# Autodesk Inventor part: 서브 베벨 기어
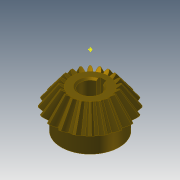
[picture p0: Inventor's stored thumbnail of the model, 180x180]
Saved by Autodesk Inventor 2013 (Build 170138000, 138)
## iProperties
Created: 2014-10
Part Number: 서브 베벨 기어
Material: Steel, Mild
Document SubType Name: Modeling
Designer: KYOUNG IL JANG
Categories: <?xml version="1.0" encoding="UTF-16"?> <MemberInstance><Categories><FamilyTemplate><FamilyTemplateParameter ValueType="xs:double" Id="1" ObjectReferenceKey="da
Mass: 134.866 g
Surface Area: 63.6518 cm^2
Volume: 17.1585 cm^3
Density: 7.86 g/cm^3
CustomPartVersion: 1
Company: 한국ATC센터
Author: KYOUNG IL JANG
Revision Number: 1
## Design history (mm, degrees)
node "맨 위 점"
node "메쉬 평면2"
sketch "톱니 본체 스케치"
  geometry: L1 (0, 0)-(18.003, -31.331); L2 (18.003, -31.331)-(21.664, -28.891); L3 (21.664, -28.891)-(0, 0); L4 (20, -30)-(0, 0); L5 (10.813, -18.818)-(13.012, -17.352); L6 (18.003, -31.331)-(10.813, -18.818); L7 (21.664, -28.891)-(13.012, -17.352); L8 (0, -39.387)-(0, 6.564) reference; L9 (0, -30)-(21.664, -30)
  constraints: 16 end point, 4 point on line, 3 perpendicular, 2 collinear, 1 horizontal alignment, 1 vertical alignment
  dimensions: "d0" = 40 diameter of L4.start L8 (= da_de); "d1" = 36.00616 diameter of L1.end L8 (= da_dfe); "d2" = 43.3282 diameter of L2.end L8 (= da_dae); "d3" = 14.4 distance between parallel lines of L2 L5 (= da_b); "d4" = 28.8906 vertical distance of L2.end L1.start (= da_ve)
revolve "톱니 본체" sketch "톱니 본체 스케치" stored, may be unused: angle "d5" = 90 deg
node "시작점"
node "톱니 평면"
sketch "시작 스케치"
  geometry: L1 (0, -23.505)-(0, 10.645) reference; L2 (-0.834, -2.928)-(0.834, -2.928); A1 r 8.898 centre (-9.698, -3.713) between (-0.834, -2.928) and (-3.903, 3.04); A2 r 8.898 centre (9.698, -3.713) between (3.903, 3.04) and (0.834, -2.928); A3 r 27.357 centre (0, -24.037) between (3.903, 3.04) and (-3.903, 3.04); 1 further point
  constraints: 6 point on circle, 3 centre point, 3 symmetric about line, 2 end point, 1 coincident, 1 perpendicular, 1 other
  dimensions: "d7" = 8.89846 radius of A1 (= fd_rr); "d8" = 9.69794 horizontal distance of point (0, -24.037) A1.centre (= fd_x); "d9" = 20.32439 vertical distance of point (0, -24.037) A1.centre (= fd_y); "d57" = 27.35701 radius of A3 (= 0.5 x fd_dva + 0.3 x da_he); "d58" = 21.10901 distance from line of A3.centre L2 (= 0.5 x fd_dva - 1.12 x da_he)
node "끝점"
  node "끝 평면"
sketch "3D 스케치 오른쪽"
  node "Helical Curve Right" dims "d65" = 229.90621 (computed from da_dm, da_delta, da_beta), "d66" = 31.5, "d67" = 40 (= da_de), "d68" = -5.88003 (= -da_delta), "d69" = 12.16458 (computed from fd_loft, da_delta)
node "끝 평면 오른쪽"
sketch "끝 스케치 오른쪽"
  geometry: L1 (0, -22.649)-(0, 12.15) reference; L2 (-0.497, -1.72)-(0.497, -1.72); A1 r 5.299 centre (-5.775, -2.187) between (-0.497, -1.72) and (-2.324, 1.834); A2 r 5.299 centre (5.775, -2.187) between (2.324, 1.834) and (0.497, -1.72); A3 r 16.291 centre (0, -14.29) between (2.324, 1.834) and (-2.324, 1.834); 1 further point
  constraints: 6 point on circle, 3 centre point, 3 symmetric about line, 2 end point, 1 coincident, 1 perpendicular, 1 other
  dimensions: "d70" = 5.77526 horizontal distance of A3.centre A1.centre (computed from fd_x, fd_ratio); "d71" = 12.10346 vertical distance of point (0, -14.29) A1.centre (computed from fd_y, fd_ratio); "d72" = 5.29916 radius of A1 (computed from fd_rr, fd_ratio); "d73" = 12.57071 distance from line of point (0, -14.29) L2 (computed from d58, fd_ratio); "d74" = 16.29149 radius of A3 (computed from d57, fd_ratio)
feature "로프트 오른쪽" sketch "끝 스케치 오른쪽" dims "d75" = 0, "d77" = 0, "d79" = 0, "d80" = 90 deg, "d85" = 20, "d92" = 90 deg, "d93" = 90 deg, "da_teethtype" = 0 [user parameter]
sketch "3D 스케치 왼쪽"
  node "Helical Curve Left" dims "d26" = 229.90621 (computed from da_dm, da_delta, da_beta), "d27" = 12.16458 (computed from fd_loft, da_delta), "d28" = 40 (= da_de), "d29" = -5.88003 (= -da_delta)
node "끝 평면 왼쪽"
sketch "끝 스케치 왼쪽" dims "d56" = 10.82768 (derived)
  geometry: L1 (0, -35.087)-(0, 18.089) reference; L2 (-0.497, -1.716)-(0.497, -1.716); A1 r 5.299 centre (-5.775, -2.183) between (-0.497, -1.716) and (-2.324, 1.838); A2 r 5.299 centre (5.775, -2.183) between (2.324, 1.838) and (0.497, -1.716); A3 r 16.291 centre (0, -14.287) between (2.324, 1.838) and (-2.324, 1.838); 2 further points; 1 other entity
  constraints: 6 point on circle, 3 centre point, 3 symmetric about line, 2 end point, 1 coincident, 2 other
  dimensions: "d30" = 5.29916 radius of A1 (computed from fd_rr, fd_ratio); "d31" = 5.77526 horizontal distance of point (0, -14.287) A1.centre (computed from fd_x, fd_ratio); "d32" = 12.10346 vertical distance of A1.centre point (0, -14.287) (computed from fd_y, fd_ratio); "d61" = 16.29149 radius of A3 (computed from d57, fd_ratio); "d62" = 12.57071 distance from line of point (0, -14.287) L2 (computed from d58, fd_ratio)
feature "로프트 왼쪽" sketch "끝 스케치 왼쪽" dims "d35" = 0, "d37" = 0, "d39" = 0, "d40" = 90 deg, "d84" = 10, "d90" = 90 deg, "d91" = 90 deg, "da_teethtype" = 0 [user parameter]
sketch "본체 스케치"
  geometry: L1 (0, -35.038)-(0, -19.531) reference; L2 (18.003, -31.331)-(10.813, -18.818) reference; L3 (10.813, -18.818)-(0, -18.818); L4 (18.003, -31.331)-(0, -31.331)
  constraints: 4 end point, 2 perpendicular, 2 point on line
revolve "본체 고정" sketch "본체 스케치" stored, may be unused: angle "d46" = 90 deg
feature "피치 지름" dims angle "d47" = 90 deg
sketch "스케치8"
  geometry: C1 r 17 at (0, 0); 1 further point
  constraints: 1 centre point, 1 coincident
  dimensions: "d94" = 34 diameter of C1
extrude "돌출1" join sketch "스케치8" distance "d95" = 10; taper "d96" = 0 deg
sketch "스케치9"
  geometry: 1 further point
hole "구멍1" sketch "스케치9" at (0, 0) diameter "d97" = 12; stored, may be unused: countersink angle "d101" = 90 deg, drill point angle "d103" = 118 deg; dims "d98" = 6, "d99" = 4, "d100" = 2, "d102" = 8
sketch "스케치10"
  geometry: 1 further point
sketch "스케치11"
  geometry: 1 further point
sketch "스케치12"
  geometry: L1 (-2, 5.657)-(-2, 7.8); L2 (-2, 7.8)-(2, 7.8); L3 (2, 7.8)-(2, 5.657); A1 r 6 centre (0, 0) between (-2, 5.657) and (2, 5.657) reference; 1 further point
  constraints: 6 end point, 2 parallel, 2 point on circle, 1 perpendicular, 1 vertical
  dimensions: "d104" = 4 distance of L1.end L2.end; "d105" = 13.8 dimension on A1 L2
extrude "돌출2" cut sketch "스케치12" stored distance "d106" = 7; taper "d107" = 0 deg
chamfer "모따기1" distance "d108" = 1; stored, may be unused: second distance "d109" = 2, angle "d110" = 45 deg
body "Solid1"
feature "로프트" dims "d17" = 0, "d18" = 90 deg, "d19" = 0, "d20" = 90 deg, "d89" = 0, "da_teethtype" = 0 [user parameter]
pattern_circular "원형 패턴" dims angle "d22" = 360 deg, "d88" = 0, "da_teethtype" = 0 [user parameter]
pattern_circular "원형 패턴 오른쪽" dims angle "d82" = 360 deg, "da_teethtype" = 0 [user parameter]
pattern_circular "원형 패턴 왼쪽" dims angle "d42" = 360 deg, "da_teethtype" = 0 [user parameter]
sketch "끝 스케치"
  geometry: L1 (0, -15.359)-(0, 6.983) reference; L2 (-0.497, -1.72)-(0.497, -1.72); A1 r 5.299 centre (-5.775, -2.187) between (-0.497, -1.72) and (-2.324, 1.834); A2 r 5.299 centre (5.775, -2.187) between (2.324, 1.834) and (0.497, -1.72); A3 r 16.291 centre (0, -14.29) between (2.324, 1.834) and (-2.324, 1.834); 1 further point
  constraints: 6 point on circle, 3 centre point, 3 symmetric about line, 2 end point, 1 coincident, 1 other
  dimensions: "d12" = 5.29916 radius of A1 (computed from fd_rr, fd_ratio); "d15" = 5.77526 horizontal distance of A1.centre point (0, -14.29) (computed from fd_x, fd_ratio); "d16" = 12.10346 vertical distance of A1.centre point (0, -14.29) (computed from fd_y, fd_ratio); "d59" = 16.29149 radius of A3 (computed from d57, fd_ratio); "d60" = 12.57071 distance from line of A3.centre L2 (computed from d58, fd_ratio)
sketch "Sketch6"
  geometry: L1 (20, -30)-(0, 0) reference; L2 (0, -37.8)-(0, 6.3) reference
body "Srf1"
other parameters: "da_b" = 14.4 [user parameter; used in 2 equation terms], "da_de" = 40 [user parameter; used in 4 equation terms], "da_dae" = 43.3282 [user parameter; used in 2 equation terms], "da_dfe" = 36.00616 [user parameter; used in 1 equation term], "da_le" = 36.05551 [user parameter; used in 1 equation term], "da_omega" = 90 deg [user parameter; used in 1 equation term], "da_beta" = 0 [user parameter; used in 2 equation terms], "da_delta" = 5.88003 [user parameter; used in 8 equation terms], "da_alpha" = 20 deg [user parameter; used in 2 equation terms], "da_he" = 4.4 [user parameter; used in 4 equation terms], "da_ve" = 28.8906 [user parameter; used in 1 equation term], "fd_dv" = 48.07402 (computed from da_de, da_delta) [user parameter; used in 1 equation term], "fd_dva" = 52.07402 (computed from da_dae, da_delta) [user parameter; used in 3 equation terms], "fd_dvb" = 45.1748 (computed from fd_dv, da_alpha) [user parameter; used in 2 equation terms], "da_zv" = 240.37008 [user parameter; used in 1 equation term], "fd_loft" = 14.62 (= da_b + 0.05 x da_he) [user parameter; used in 4 equation terms], "fd_ratio" = 5.95514 (computed from da_le, fd_loft) [user parameter; used in 15 equation terms], "fd_rr" = 8.89846 (computed from fd_dd, fd_dvb) [user parameter; used in 6 equation terms], "fd_angle" = 0.66075 (computed from da_zv) [user parameter; used in 4 equation terms], "fd_x1" = 1.58709 (computed from da_dvw, fd_angle) [user parameter; used in 1 equation term], "fd_y1" = 23.98456 (computed from da_dvw, fd_angle) [user parameter; used in 1 equation term], "fd_x2" = 8.11084 (computed from fd_rr, fd_angle2, fd_angle) [user parameter; used in 1 equation term], "fd_y2" = 3.66016 (computed from fd_rr, fd_angle2, fd_angle) [user parameter; used in 1 equation term], "fd_x" = 9.69794 (= fd_x1 + fd_x2) [user parameter; used in 4 equation terms], "fd_y" = 20.32439 (= fd_y1 - fd_y2) [user parameter; used in 4 equation terms], "fd_angle2" = 3.57832 (computed from fd_dvb, fd_dd, da_alpha) [user parameter; used in 2 equation terms], "fd_dd" = 48.55402 (= fd_dva - 0.8 x da_he) [user parameter; used in 2 equation terms], "da_dvw" = 48.07402 [user parameter; used in 2 equation terms], "d11" = 14.62 (= fd_loft), "da_dm" = 32.01232 [user parameter; used in 2 equation terms], "da_x" = 0 [user parameter], "da_m" = 2 [user parameter], "d48" = 0, "d49" = 0, "d50" = 90 deg (= da_omega), "d51" = 9 deg (computed from da_z), "d52" = 0, "d53" = 0, "d54" = 0
